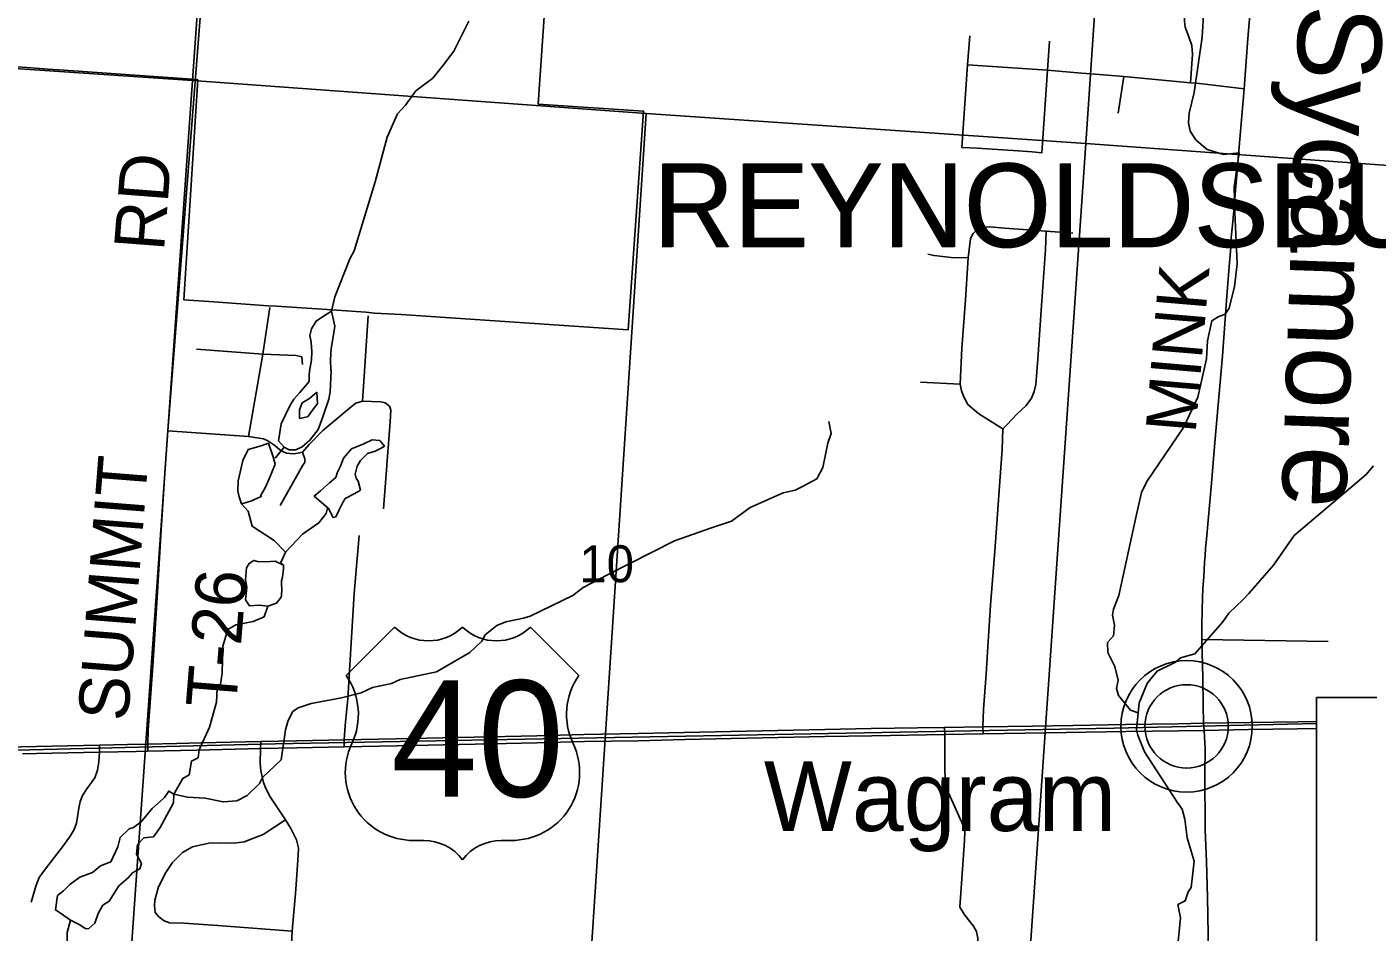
# Model space of a CAD drawing. Extents: x 0 to 34, y 0 to 26.1.
# Drawn here: x 26.701 to 28.22, y 19.127 to 20.153 of the extents above; entities that cross this region are included whole.
import ezdxf

# ---------------------------------------------------------------- set-up
doc = ezdxf.new("R2010")
doc.units = 0
for name, color, linetype in [('GM_X_Corporation_Text', 7, 'Continuous'), ('GM_X_County_Road', 7, 'Continuous'), ('GM_X_County_Road_Text', 7, 'Continuous'), ('GM_X_Minor_Lake', 7, 'Continuous'), ('GM_X_Minor_River', 7, 'Continuous'), ('GM_X_Minor_River_Text', 7, 'Continuous'), ('GM_X_Rail_Line', 7, 'Continuous'), ('GM_X_Section', 7, 'Continuous'), ('GM_X_Section_Text', 7, 'Continuous'), ('GM_X_Township_Road', 7, 'Continuous'), ('GM_X_Township_Road_Text', 7, 'Continuous'), ('GM_X_Unincorporated', 7, 'Continuous'), ('GM_X_Unincorporated_Location', 7, 'Continuous'), ('GM_X_Unincorporated_Text', 7, 'Continuous'), ('GM_X_US_Location', 7, 'Continuous'), ('GM_X_US_Route', 7, 'Continuous'), ('GM_X_US_Shield', 7, 'Continuous'), ('SC_Scratch1', 7, 'Continuous'), ('SH_Data', 7, 'Continuous')]:
    doc.layers.add(name, color=color, linetype=linetype)

msp = doc.modelspace()

# ---------------------------------------------------------------- linework, layer by layer
at = {"layer": 'GM_X_County_Road'}
for points in [[(28.0916, 20.233), (28.0838, 20.1395), (28.0793, 20.0827), (28.0734, 20.0123), (28.0699, 19.972), (28.0686, 19.9543), (28.0673, 19.9405), (28.0663, 19.9281), (28.0649, 19.9142), (28.0643, 19.9029), (28.0628, 19.8857), (28.0602, 19.8526), (28.0582, 19.8269), (28.0564, 19.801), (28.0549, 19.7802), (28.0512, 19.7374), (28.0464, 19.682), (28.0424, 19.6358), (28.0367, 19.5724), (28.0358, 19.5624), (28.0352, 19.5535), (28.0347, 19.5465), (28.0336, 19.5302), (28.0328, 19.5161), (28.0324, 19.5065), (28.0319, 19.4916), (28.0317, 19.476), (28.0317, 19.4661), (28.0317, 19.4588), (28.0326, 19.4154), (28.0329, 19.3845), (28.0335, 19.3642), (28.0342, 19.3559)], [(28.0342, 19.3559), (28.0352, 19.3352), (28.035, 19.3074), (28.0354, 19.2433), (28.0368, 19.2074), (28.0379, 19.1672), (28.039, 19.1041)]]:
    msp.add_lwpolyline(points, dxfattribs=at)
at = {"layer": 'GM_X_Minor_Lake'}
for points in [[(27.0459, 19.8307), (27.0368, 19.825), (27.0285, 19.8194), (27.0232, 19.8107), (27.0213, 19.8031), (27.0228, 19.7955), (27.0235, 19.7845), (27.0231, 19.7757), (27.0208, 19.7628), (27.0204, 19.7587), (27.0204, 19.7518), (27.0204, 19.7511), (27.014, 19.7435), (27.0102, 19.7386), (27.0033, 19.731), (26.9991, 19.7242), (26.9889, 19.7033), (26.9858, 19.684), (26.9922, 19.6767)], [(26.9922, 19.6767), (26.9979, 19.6737), (27.0055, 19.6737), (27.0127, 19.6771), (27.0214, 19.6846), (27.0309, 19.6968), (27.0362, 19.7112), (27.0427, 19.7309), (27.0442, 19.7392), (27.0454, 19.7632), (27.045, 19.7643), (27.0447, 19.7757), (27.0455, 19.7886), (27.0478, 19.8015), (27.0497, 19.8136), (27.0459, 19.8307)], [(27.0291, 19.7389), (27.0211, 19.7317), (27.0128, 19.7268), (27.0097, 19.7188), (27.0097, 19.7093)], [(27.0188, 19.7112), (27.0215, 19.7142), (27.0215, 19.7146), (27.0302, 19.726), (27.0291, 19.7389)], [(27.0097, 19.7093), (27.0188, 19.7112)], [(26.9744, 19.6813), (26.9664, 19.6782), (26.9516, 19.6741), (26.9456, 19.6616), (26.9402, 19.6384), (26.9399, 19.627), (26.9414, 19.6206), (26.944, 19.6126), (26.9546, 19.6156)], [(26.9546, 19.6156), (26.9663, 19.6209), (26.9656, 19.6217), (26.9709, 19.6308), (26.9751, 19.641), (26.9785, 19.649), (26.9819, 19.6574), (26.98, 19.6657), (26.9744, 19.6813)], [(27.0789, 19.628), (27.0762, 19.6382), (27.074, 19.6416), (27.0725, 19.6462), (27.0751, 19.6553), (27.0789, 19.6617), (27.0865, 19.6697), (27.0952, 19.6723), (27.102, 19.6757), (27.1058, 19.678), (27.1006, 19.6841), (27.0918, 19.6849), (27.0824, 19.6803), (27.0687, 19.6747), (27.0596, 19.6644), (27.0562, 19.6553), (27.0528, 19.6485), (27.0509, 19.6424), (27.0437, 19.6364), (27.0334, 19.6273), (27.0262, 19.6212), (27.0425, 19.6072)], [(27.0425, 19.6072), (27.0477, 19.5969), (27.0508, 19.5977), (27.0546, 19.6056), (27.0588, 19.614), (27.0614, 19.6185), (27.0724, 19.6242), (27.0789, 19.628)], [(26.9893, 19.5215), (26.9893, 19.5253), (26.9904, 19.5295), (26.9916, 19.5393), (26.9916, 19.5431), (26.9821, 19.5477), (26.9712, 19.5469), (26.9621, 19.5473), (26.9579, 19.5485), (26.9526, 19.5451), (26.9496, 19.5401), (26.9484, 19.5265), (26.9499, 19.5181), (26.9484, 19.5037), (26.9529, 19.4969), (26.9639, 19.4976), (26.9737, 19.4968)], [(26.9737, 19.4968), (26.9836, 19.4999), (26.9889, 19.5067), (26.9893, 19.5086), (26.9897, 19.5158), (26.9893, 19.5215)], [(26.8675, 19.2837), (26.8656, 19.2848), (26.8615, 19.2871), (26.8566, 19.2799), (26.8429, 19.2674), (26.8304, 19.2522), (26.8217, 19.2458), (26.8168, 19.2443), (26.8066, 19.2348), (26.8039, 19.2242), (26.7959, 19.2071), (26.7842, 19.2026), (26.7751, 19.195), (26.7607, 19.1897), (26.7494, 19.1814), (26.7422, 19.1742), (26.7357, 19.1689), (26.7334, 19.1526), (26.7391, 19.1491), (26.7504, 19.1411)], [(26.7504, 19.1411), (26.7607, 19.1358), (26.7659, 19.1324), (26.7682, 19.1313), (26.7709, 19.1316), (26.7777, 19.1377), (26.7815, 19.1487), (26.7868, 19.1578), (26.794, 19.1627), (26.805, 19.1798), (26.8156, 19.1889), (26.8205, 19.1946), (26.8288, 19.1991), (26.8307, 19.2052), (26.8251, 19.2158), (26.8262, 19.2268), (26.8334, 19.2344), (26.8444, 19.2355), (26.852, 19.2458), (26.8668, 19.2738), (26.8675, 19.2837)]]:
    msp.add_lwpolyline(points, dxfattribs=at)
at = {"layer": 'GM_X_Minor_River'}
for points in [[(27.0459, 19.8307), (27.0498, 19.847), (27.0665, 19.8899), (27.0714, 19.899), (27.0955, 19.9771), (27.1088, 20.0276), (27.1206, 20.0541), (27.1297, 20.064), (27.1415, 20.0803), (27.1605, 20.0946), (27.1726, 20.1098), (27.1844, 20.1253), (27.2015, 20.1591)], [(27.9596, 19.376), (27.9508, 19.3789), (27.9372, 19.3956), (27.935, 19.4032), (27.9369, 19.4127), (27.9331, 19.4283), (27.9252, 19.4442), (27.9248, 19.4556), (27.9313, 19.4632), (27.9328, 19.475), (27.9302, 19.4864), (27.9314, 19.4932), (27.9374, 19.5087), (27.9569, 19.5971), (27.9631, 19.6252), (27.9691, 19.6377), (28.0109, 19.6991), (28.0239, 19.7268), (28.0269, 19.7333), (28.0368, 19.7769), (28.038, 19.797), (28.043, 19.8198), (28.0502, 19.8243), (28.0578, 19.8273), (28.0623, 19.8341), (28.0684, 19.8588), (28.0715, 19.8842), (28.069, 19.9427), (28.0683, 19.9715), (28.0737, 20.0102), (28.0559, 20.008), (28.0377, 20.0137), (28.0309, 20.0194), (28.0248, 20.0248), (28.0184, 20.0347), (28.0165, 20.0441), (28.0173, 20.0551), (28.023, 20.0783), (28.0319, 20.1409), (28.0338, 20.172)], [(26.9889, 19.3226), (26.9939, 19.3564), (26.9969, 19.367), (27.0019, 19.3772), (27.0083, 19.3814), (27.0227, 19.3863), (27.0572, 19.3927), (27.0795, 19.3983), (27.0924, 19.4044), (27.114, 19.4089), (27.1235, 19.4134), (27.1648, 19.4224), (27.2027, 19.444), (27.216, 19.4568), (27.2198, 19.464), (27.233, 19.4746), (27.2433, 19.4788), (27.2634, 19.4829), (27.2709, 19.4852), (27.3191, 19.5086), (27.3308, 19.5177), (27.3593, 19.5324), (27.4343, 19.5706), (27.4752, 19.5849), (27.4987, 19.5929), (27.52, 19.6084), (27.5575, 19.625), (27.5708, 19.628), (27.5791, 19.6321), (27.5954, 19.6408), (27.6022, 19.6537), (27.608, 19.6811), (27.6118, 19.692), (27.6092, 19.7057)], [(26.9922, 19.6767), (26.982, 19.6642)], [(28.004, 19.1093), (28.006, 19.1282), (28.0075, 19.1438), (28.0045, 19.1586), (28.0125, 19.1628), (28.0159, 19.173), (28.0193, 19.1779), (28.0228, 19.2079), (28.0149, 19.2341), (28.0123, 19.2554), (28.0093, 19.2668), (28.0036, 19.2748), (27.9666, 19.3318), (27.9591, 19.3504), (27.9576, 19.3565), (27.9607, 19.3872), (27.9698, 19.4092), (27.9736, 19.4145), (27.9808, 19.4229), (28.0017, 19.4331), (28.0074, 19.438), (28.0237, 19.4425), (28.0552, 19.4789), (28.062, 19.4887), (28.0779, 19.5039), (28.0848, 19.5111), (28.1128, 19.5429), (28.136, 19.5766), (28.2176, 19.6459), (28.2259, 19.6554)], [(26.9939, 19.5579), (26.981, 19.5708), (26.9561, 19.5872), (26.9516, 19.6043), (26.944, 19.6126)], [(26.9916, 19.5431), (26.9886, 19.5462), (26.9939, 19.5579), (27.0132, 19.578), (27.0314, 19.5909), (27.0398, 19.6015), (27.0413, 19.6075)], [(26.8675, 19.2837), (26.8774, 19.3015), (26.8846, 19.3057), (26.8873, 19.3212), (26.8948, 19.325), (26.896, 19.3338), (26.9077, 19.3596), (26.9157, 19.388), (26.9165, 19.4032), (26.9203, 19.4081), (26.9222, 19.4206), (26.923, 19.4514), (26.9283, 19.4703), (26.9374, 19.4756), (26.9571, 19.4794), (26.9696, 19.4847), (26.9737, 19.4968)], [(26.9889, 19.3226), (26.9678, 19.3026), (26.9644, 19.2957), (26.9504, 19.2821), (26.9387, 19.276), (26.9231, 19.2749), (26.9027, 19.2791), (26.8827, 19.2803), (26.8675, 19.2837)], [(26.7504, 19.1411), (26.7466, 19.1271), (26.7466, 19.1032), (26.7451, 19.0892), (26.7413, 19.0793), (26.7318, 19.0622), (26.7182, 19.0471), (26.7185, 19.0288), (26.7166, 19.0239), (26.7125, 19.0137), (26.7121, 19.0049), (26.7185, 18.9738), (26.7128, 18.9632), (26.7177, 18.9514), (26.7199, 18.9321), (26.7222, 18.9268), (26.7275, 18.9207), (26.7316, 18.9157), (26.7324, 18.9108), (26.7267, 18.8971), (26.6911, 18.8642)]]:
    msp.add_lwpolyline(points, dxfattribs=at)
at = {"layer": 'GM_X_Rail_Line'}
msp.add_lwpolyline([(25.3226, 19.2999), (25.5312, 19.3051), (26.9819, 19.3408), (27.9322, 19.3586), (28.1615, 19.3637)], dxfattribs=at)
at = {"layer": 'GM_X_Section'}
for points in [[(25.926, 20.6906), (26.2619, 20.6708), (26.7939, 20.6382), (26.9267, 20.63), (26.8884, 20.0918), (26.3915, 20.1255), (26.3885, 20.1257), (25.892, 20.1588)], [(26.9267, 20.63), (27.3172, 20.6101), (27.8347, 20.5796), (27.9376, 20.5735), (27.9001, 20.0205), (27.4021, 20.0547), (26.8884, 20.0918)], [(27.9376, 20.5735), (28.3638, 20.5476), (28.9502, 20.5089), (28.9104, 19.9472), (28.4191, 19.9828), (27.9001, 20.0205)], [(26.3915, 20.1255), (26.8884, 20.0918), (26.8184, 19.0949), (26.3256, 19.1287)], [(26.8884, 20.0918), (27.4021, 20.0547), (27.3369, 19.0584), (26.8184, 19.0949)], [(27.4021, 20.0547), (27.9001, 20.0205), (27.8314, 19.025), (27.3369, 19.0584)]]:
    msp.add_lwpolyline(points, close=True, dxfattribs=at)
msp.add_lwpolyline([(28.1615, 19.0015), (27.8314, 19.025), (27.9001, 20.0205), (28.4191, 19.9828), (28.3774, 19.3933)], dxfattribs=at)
at = {"layer": 'GM_X_Township_Road'}
for p, q in [((27.9367, 20.0551), (27.943, 20.0965)), ((27.0811, 19.7287), (27.0874, 19.8256)), ((27.7131, 19.7502), (27.7579, 19.7481)), ((28.0317, 19.4588), (28.1747, 19.4565))]:
    msp.add_line(p, q, dxfattribs=at)
for points in [[(26.8913, 20.0905), (26.9136, 20.3771), (26.9307, 20.6339)], [(28.0186, 20.0892), (28.021, 20.1217), (28.0201, 20.1316), (28.0167, 20.1416), (28.0136, 20.1492), (28.0126, 20.1524), (28.0122, 20.1553), (28.0118, 20.1592), (28.0119, 20.1643), (28.0126, 20.1731), (28.015, 20.207), (28.0137, 20.2257), (28.0154, 20.2392)], [(27.7596, 20.0159), (27.7663, 20.1098), (27.7687, 20.1427)], [(27.8504, 20.01), (27.8567, 20.1037), (27.8589, 20.1364)], [(27.7663, 20.1098), (27.8567, 20.1037), (27.8953, 20.1002), (27.9108, 20.099)], [(27.9108, 20.099), (27.9152, 20.0987), (27.943, 20.0965), (28.0186, 20.0892), (28.029, 20.0885), (28.0793, 20.0827)], [(26.8379, 19.3324), (26.8379, 19.3405), (26.8381, 19.3566), (26.8435, 19.4289), (26.8484, 19.5064), (26.8526, 19.577), (26.8574, 19.6532), (26.8605, 19.6951), (26.8913, 20.0905)], [(27.7596, 20.0159), (27.7772, 20.0155), (27.8236, 20.0122), (27.8392, 20.0111), (27.8504, 20.01)], [(27.8063, 19.6973), (27.7788, 19.7144), (27.7666, 19.725), (27.7618, 19.7336), (27.7595, 19.7405), (27.7579, 19.7481), (27.7598, 19.7887), (27.7638, 19.8437), (27.7669, 19.8911), (27.7695, 19.9132), (27.7725, 19.9187), (27.7768, 19.9232), (27.7819, 19.9256), (27.7914, 19.9264), (27.808, 19.9248)], [(27.7838, 19.352), (27.7836, 19.3599), (27.7841, 19.3798), (27.7872, 19.4196), (27.7897, 19.4567), (27.7923, 19.4978), (27.7974, 19.5639), (27.8021, 19.6277), (27.8054, 19.6742), (27.8063, 19.6973), (27.8111, 19.7024), (27.822, 19.7141), (27.8325, 19.7237), (27.8388, 19.7323), (27.8417, 19.7399), (27.8437, 19.7476), (27.8458, 19.7763), (27.85, 19.837), (27.8543, 19.9006), (27.8553, 19.9214)], [(27.808, 19.9248), (27.8553, 19.9214), (27.8855, 19.9192)], [(27.7213, 19.8954), (27.7283, 19.8936), (27.7478, 19.8915), (27.7669, 19.8911)], [(26.9518, 19.6888), (26.968, 19.7821), (26.9761, 19.8348)], [(26.893, 19.7876), (26.968, 19.7821), (27.006, 19.7805), (27.0121, 19.779), (27.0131, 19.7704)], [(26.8605, 19.6951), (26.9518, 19.6888), (26.9687, 19.6861), (26.9737, 19.6839), (26.9817, 19.6784), (26.9875, 19.6737), (26.9914, 19.6714), (26.995, 19.6698), (27.0028, 19.6692), (27.0077, 19.6698), (27.0131, 19.6711), (27.0205, 19.6797), (27.0362, 19.6955), (27.0681, 19.7224), (27.0733, 19.7265), (27.0811, 19.7287), (27.1016, 19.7279), (27.1068, 19.7268), (27.1115, 19.7232)], [(27.1049, 19.6067), (27.1124, 19.7055), (27.1132, 19.7185), (27.1115, 19.7232)], [(26.9878, 19.6108), (27.0136, 19.6562), (27.0155, 19.6595), (27.0155, 19.6634), (27.0131, 19.6711)], [(27.0604, 19.3372), (27.0604, 19.3452), (27.0612, 19.3614), (27.0644, 19.3918), (27.0679, 19.4487), (27.0717, 19.5111), (27.0773, 19.5766)], [(27.7402, 19.3592), (27.7404, 19.3514), (27.7406, 19.3144), (27.7409, 19.2983), (27.7418, 19.2928), (27.7435, 19.2876), (27.7464, 19.2809), (27.7614, 19.2481), (27.763, 19.2412), (27.7628, 19.2311), (27.7576, 19.1556), (27.7633, 19.1468)], [(26.7059, 19.1612), (26.7115, 19.1806), (26.715, 19.1893), (26.7207, 19.1978), (26.7423, 19.2256), (26.7501, 19.2361), (26.7543, 19.2437), (26.757, 19.2507), (26.7584, 19.258), (26.7596, 19.2677), (26.7613, 19.2754), (26.7639, 19.2823), (26.7689, 19.2896), (26.7777, 19.3023), (26.7808, 19.3108), (26.7825, 19.3205), (26.7831, 19.3311), (26.7831, 19.3392)], [(26.9974, 19.0598), (27.0015, 19.1287), (27.0053, 19.1757), (27.0082, 19.2146), (27.0084, 19.2231), (27.0064, 19.2319), (27, 19.2448), (26.9938, 19.2546), (26.9833, 19.2705), (26.9765, 19.2805), (26.9715, 19.2901), (26.9688, 19.297), (26.9659, 19.3103), (26.965, 19.3189), (26.9654, 19.3353), (26.9658, 19.3432)], [(26.8503, 19.1448), (26.8462, 19.1495), (26.8456, 19.1574), (26.8459, 19.1635), (26.85, 19.1787), (26.8581, 19.1951), (26.8658, 19.2063), (26.8771, 19.2178), (26.8886, 19.2239), (26.907, 19.2283), (26.9202, 19.2287), (26.9355, 19.2283), (26.9471, 19.2299), (26.9684, 19.2379), (26.9938, 19.2546)], [(26.8503, 19.1448), (26.8564, 19.1404), (26.8625, 19.1381), (26.8786, 19.1375), (26.9171, 19.1349), (27.0015, 19.1287)], [(27.7744, 19.0792), (27.7775, 19.1052), (27.778, 19.1207), (27.7763, 19.1283), (27.7729, 19.1342), (27.7633, 19.1468)]]:
    msp.add_lwpolyline(points, dxfattribs=at)
at = {"layer": 'GM_X_Unincorporated'}
for radius in [0.0744, 0.0472]:
    msp.add_circle((28.0143, 19.3605), radius, dxfattribs=at)
at = {"layer": 'GM_X_Unincorporated_Location'}
msp.add_line((28.0143, 19.3605), (28.0143, 19.3605), dxfattribs=at)
at = {"layer": 'GM_X_US_Route'}
for points in [[(26.6958, 19.3293), (26.7118, 19.3296), (26.7651, 19.3308), (26.7831, 19.3311), (26.8246, 19.3321), (26.8379, 19.3324), (26.8934, 19.3337), (26.9654, 19.3353), (27.0066, 19.336), (27.0604, 19.3372), (27.1204, 19.3385), (27.1728, 19.3396), (27.2262, 19.3408), (27.2786, 19.342), (27.3323, 19.3432), (27.393, 19.3442), (27.4459, 19.3455), (27.4986, 19.3468), (27.5516, 19.3478), (27.6047, 19.349), (27.6577, 19.3499), (27.7404, 19.3514), (27.7838, 19.352), (27.8551, 19.3531), (27.9458, 19.3546), (28.0055, 19.3554), (28.0342, 19.3559), (28.0845, 19.3568), (28.1393, 19.3577), (28.1615, 19.358)], [(26.7831, 19.3392), (26.8148, 19.34), (26.8379, 19.3405), (26.8709, 19.3411), (26.8978, 19.3418), (26.9658, 19.3432), (27.0065, 19.3441), (27.0604, 19.3452), (27.1187, 19.3465), (27.1717, 19.3476), (27.225, 19.3488), (27.2784, 19.3499), (27.3315, 19.3512), (27.3931, 19.3523), (27.4451, 19.3535), (27.498, 19.3547), (27.5514, 19.3558), (27.6045, 19.3569), (27.6571, 19.3579), (27.7097, 19.3587), (27.7402, 19.3592), (27.7836, 19.3599), (27.8396, 19.3608), (27.8854, 19.3615), (27.9456, 19.3625), (28.0052, 19.3635), (28.0335, 19.3642), (28.086, 19.3649), (28.1408, 19.3658), (28.1615, 19.3661)], [(25.8397, 19.3204), (25.8684, 19.3209), (25.8962, 19.3215), (25.9541, 19.3228), (26.0074, 19.3239), (26.0593, 19.325), (26.1127, 19.3261), (26.1662, 19.327), (26.2193, 19.3282), (26.2732, 19.329), (26.3251, 19.3302), (26.3834, 19.3311), (26.4462, 19.3325), (26.4993, 19.3335), (26.55, 19.3344), (26.6045, 19.3355), (26.6587, 19.3367), (26.7118, 19.3377), (26.765, 19.3389), (26.7831, 19.3392)]]:
    msp.add_lwpolyline(points, dxfattribs=at)
at = {"layer": 'GM_X_US_Shield'}
for p, q in [((27.1173, 19.473), (27.0624, 19.4181)), ((27.326, 19.4181), (27.2711, 19.473)), ((27.1393, 19.2313), (27.1503, 19.2313)), ((27.2381, 19.2313), (27.2491, 19.2313))]:
    msp.add_line(p, q, dxfattribs=at)
for centre, radius, start, end in [((27.1558, 19.5122), 0.0549, 225.573, 314.427), ((27.2327, 19.5122), 0.0549, 225.573, 314.427), ((26.9994, 19.374), 0.0769, 334.5471, 35.0009), ((27.389, 19.374), 0.0769, 144.9991, 205.4529), ((27.1384, 19.3082), 0.0769, 154.8319, 270.6383), ((27.25, 19.3082), 0.0769, 269.3617, 25.1681), ((27.1503, 19.1764), 0.0549, 36.8699, 90), ((27.2381, 19.1764), 0.0549, 90, 143.1301)]:
    msp.add_arc(centre, radius, start, end, dxfattribs=at)
at = {"layer": 'SC_Scratch1'}
msp.add_lwpolyline([(26.6845, 20.1077), (26.701, 20.1065), (26.7245, 20.1049), (26.7427, 20.1036), (26.8876, 20.0933), (26.8945, 20.0928), (26.8785, 19.8436), (26.9125, 19.8413), (26.974, 19.8369), (26.9835, 19.8365), (27.0408, 19.8326), (27.0849, 19.8296), (27.0944, 19.8286), (27.1249, 19.8269), (27.3818, 19.8095), (27.3992, 20.0574), (27.2799, 20.0653), (27.2988, 20.3406), (26.9112, 20.3627), (26.9194, 20.4905), (26.9305, 20.6345), (26.8, 20.64), (26.7968, 20.64), (26.8139, 20.9)], dxfattribs=at)
at = {"layer": 'SH_Data'}
msp.add_lwpolyline([(28.1615, 19.3933), (29.8402, 19.3933), (29.8402, 18.5533), (28.1615, 18.5533)], close=True, dxfattribs=at)

# ---------------------------------------------------------------- texts
at = {"layer": 'GM_X_Corporation_Text'}
for p in [(27.4098, 19.9031), (27.411, 19.9034)]:
    msp.add_text('REYNOLDSBURG', height=0.094697, rotation=0, dxfattribs=at).set_placement(p)
at = {"layer": 'GM_X_County_Road_Text'}
msp.add_text('MINK', height=0.05682, rotation=85.1744, dxfattribs=at).set_placement((28.0244, 19.6914))
at = {"layer": 'GM_X_Minor_River_Text'}
msp.add_text('Sycamore', height=0.09469, rotation=268.0002, dxfattribs=at).set_placement((28.1417, 20.1785))
at = {"layer": 'GM_X_Section_Text'}
msp.add_text('10', height=0.04186, rotation=0, dxfattribs=at).set_placement((27.3263, 19.5237))
at = {"layer": 'GM_X_Township_Road_Text'}
for s, rotation, p in [('RD', 85.5641, (26.8561, 19.8979)), ('SUMMIT', 85.5226, (26.8152, 19.3654)), ('T-26', 85.3834, (26.9375, 19.3799))]:
    msp.add_text(s, height=0.05682, rotation=rotation, dxfattribs=at).set_placement(p)
at = {"layer": 'GM_X_Unincorporated_Text'}
msp.add_text('Wagram', height=0.07898, rotation=0, dxfattribs=at).set_placement((27.5355, 19.242))
at = {"layer": 'GM_X_US_Location'}
for s, p in [('0', (27.1941, 19.3456)), ('/', (27.1942, 19.3456))]:
    msp.add_text(s, height=0.000189, dxfattribs=at).set_placement(p)
msp.add_text('40', height=0.000189, rotation=0, dxfattribs=at).set_placement((27.155, 19.3064))
at = {"layer": 'GM_X_US_Shield'}
msp.add_text('40', height=0.13184, dxfattribs=at).set_placement((27.1133, 19.2807))

doc.saveas('drawing.dxf')
